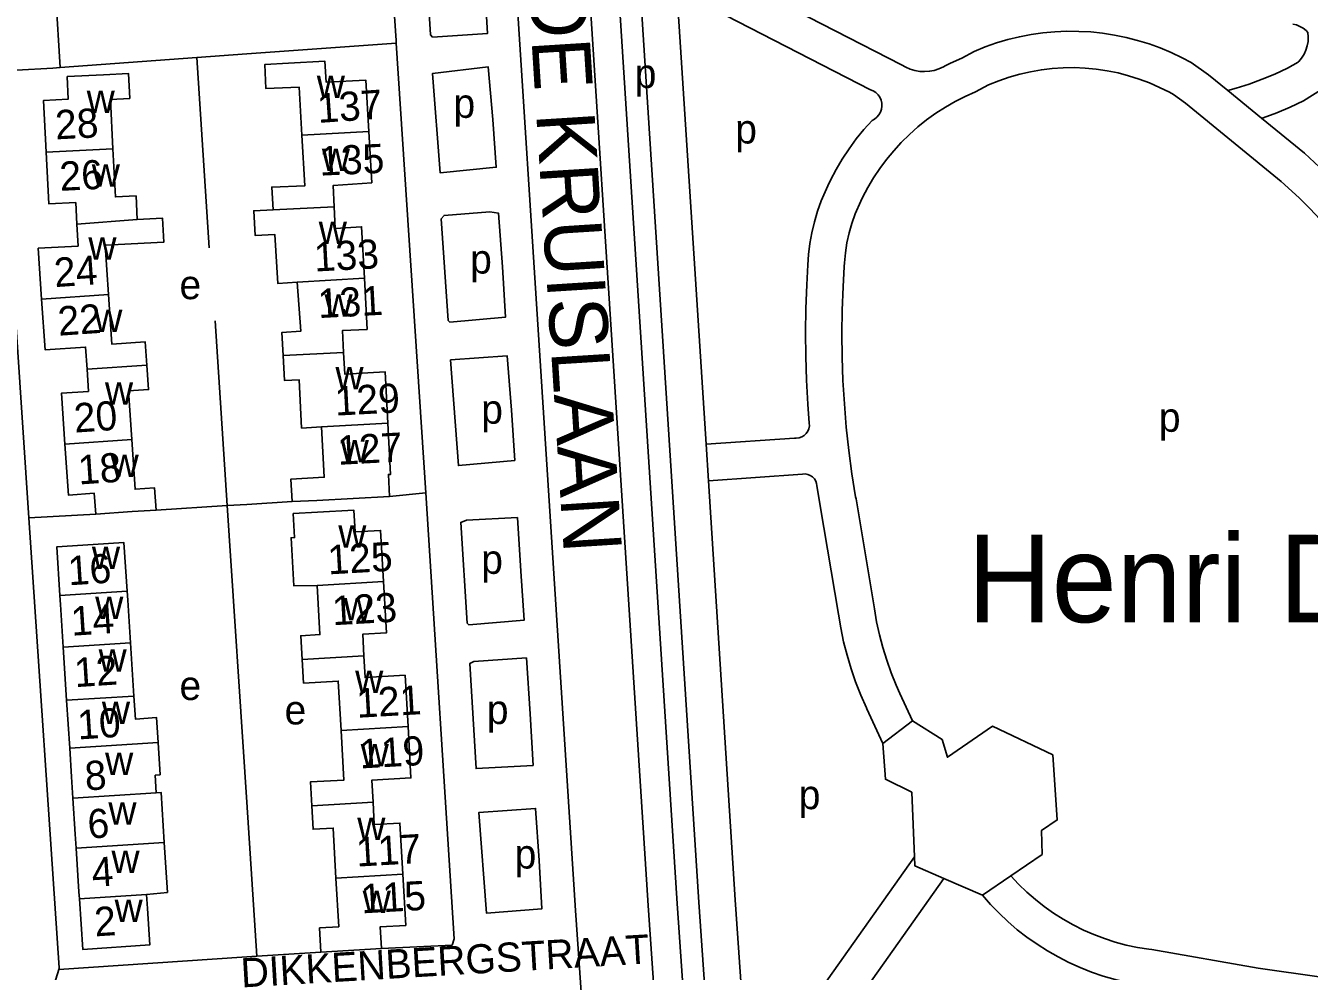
# Model space of a CAD drawing. Extents: x 159675 to 162108, y 386471 to 388472.
# Drawn here: x 160669.6 to 160845.9, y 388101.4 to 388231.2 of the extents above; entities that cross this region are included whole.
import ezdxf

# ---------------------------------------------------------------- set-up
doc = ezdxf.new("R2010")
doc.units = 0
for name, color, linetype in [('BLT_Basislijn', 7, 'Continuous'), ('BLT_Bebouwing', 7, 'Continuous'), ('BLT_Centroide', 7, 'Continuous'), ('BLT_Huisnummer', 7, 'Continuous'), ('BLT_Huisnummer_ tussenligend', 7, 'Continuous'), ('BLT_Onderverdeling_panden', 7, 'Continuous'), ('BLT_Sport_parknaam', 7, 'Continuous'), ('BLT_Straatnaam_hoofdweg', 7, 'Continuous'), ('BLT_Straatnaam_verkleind', 7, 'Continuous')]:
    doc.layers.add(name, color=color, linetype=linetype)

msp = doc.modelspace()

# ---------------------------------------------------------------- linework, layer by layer
at = {"layer": 'BLT_Basislijn'}
for p, q in [((160759.06, 388236.07), (160785.61, 388222.41)), ((160769.66, 388236.24), (160789.89, 388225.83)), ((160720.52, 388228.83), (160700, 388227.33)), ((160724.58, 388167.11), (160720.52, 388228.83)), ((160693.14, 388226.83), (160674.36, 388225.46)), ((160700, 388227.33), (160693.14, 388226.83)), ((160694.84, 388200.7), (160693.14, 388226.83)), ((160798.16, 388226.75), (160799.85, 388227.69)), ((160829.66, 388226.14), (160832.05, 388224.46)), ((160842.87, 388225.37), (160844.34, 388226.2)), ((160670.07, 388163.65), (160665.9, 388225.64)), ((160832.05, 388224.46), (160834.68, 388222.3)), ((160800.06, 388222.12), (160801.83, 388223.1)), ((160847.89, 388222.68), (160845.07, 388220.88)), ((160828.88, 388220.59), (160827.21, 388221.78)), ((160834.68, 388222.3), (160839.33, 388218.5)), ((160828.88, 388220.59), (160842.03, 388209.83)), ((160839.33, 388218.5), (160845.19, 388213.7)), ((160845.19, 388213.7), (160847.98, 388211.17)), ((160779.76, 388209.24), (160778.85, 388207.16)), ((160844.5, 388207.58), (160842.03, 388209.83)), ((160784.29, 388207.11), (160783.52, 388205.38)), ((160777.02, 388198.38), (160776.9, 388195.64)), ((160782.01, 388198.14), (160781.89, 388195.38)), ((160695.64, 388190.71), (160697.32, 388165.35)), ((160775.21, 388174.59), (160763.05, 388173.75)), ((160763.05, 388173.75), (160763.37, 388168.76)), ((160776.29, 388169.65), (160763.37, 388168.76)), ((160778.26, 388168.12), (160778.73, 388165.32)), ((160719.6, 388166.58), (160724.58, 388167.11)), ((160783.64, 388166.25), (160786.17, 388151.17)), ((160697.32, 388165.35), (160687.56, 388164.73)), ((160697.32, 388165.35), (160700, 388165.51)), ((160697.32, 388165.35), (160700, 388124.64)), ((160700, 388165.51), (160706.22, 388165.88)), ((160778.73, 388165.32), (160781.22, 388150.44)), ((160679.26, 388164.17), (160670.07, 388163.65)), ((160789.66, 388139.56), (160791.4, 388135.79)), ((160785.14, 388137.43), (160787.33, 388132.7)), ((160791.4, 388135.79), (160787.33, 388132.7)), ((160700, 388124.64), (160701.39, 388103.47)), ((160768.89, 388084.92), (160791.66, 388117.13)), ((160769.44, 388077.03), (160795.69, 388114.17)), ((160795.69, 388114.17), (160800.99, 388111.86)), ((160800.99, 388111.86), (160804.9, 388114.53)), ((160824.24, 388104.4), (160838.87, 388101.86)), ((160674.19, 388101.68), (160700, 388103.38)), ((160700, 388103.38), (160701.39, 388103.47)), ((160701.39, 388103.47), (160710.18, 388104.06)), ((160674.19, 388101.68), (160672.69, 388096.81)), ((160838.87, 388101.86), (160847.54, 388100.6))]:
    msp.add_line(p, q, dxfattribs=at)
for points in [[(160742.52, 388317.92), (160742.34, 388309.14), (160755.09, 388110.44), (160760.41, 388033.7)], [(160731.91, 388315.5), (160745.11, 388109.78), (160749.09, 388052.46)], [(160700, 388255.3), (160716.48, 388256.42), (160718.66, 388256.05), (160720.5, 388229.18), (160720.52, 388228.83)], [(160732.47, 388240.29), (160733.07, 388230.16), (160725.52, 388229.65), (160725.2, 388229.97), (160723.93, 388250.53), (160731.59, 388251.02)], [(160750.66, 388241.94), (160759.08, 388110.71), (160762.15, 388066.46)], [(160753.66, 388242.14), (160762.08, 388110.91), (160765.14, 388066.67), (160762.15, 388066.46)], [(160759.06, 388236.07), (160763.05, 388173.75)], [(160843.61, 388231.42), (160844.11, 388231.31), (160844.59, 388231.12), (160845.03, 388230.86), (160845.43, 388230.54), (160845.67, 388230.28)], [(160799.85, 388227.69), (160801.37, 388228.3), (160802.91, 388228.84), (160804.49, 388229.3), (160806.08, 388229.69), (160807.69, 388230), (160809.31, 388230.23), (160810.95, 388230.38), (160812.58, 388230.45), (160814.22, 388230.43), (160815.86, 388230.35), (160817.49, 388230.18), (160819.11, 388229.93), (160820.72, 388229.6), (160822.3, 388229.19), (160823.87, 388228.71), (160825.41, 388228.15), (160826.92, 388227.52), (160828.4, 388226.81), (160829.66, 388226.14)], [(160845.67, 388230.28), (160845.73, 388229.66), (160845.7, 388229.05), (160845.59, 388228.44), (160845.41, 388227.85), (160845.15, 388227.28), (160844.82, 388226.76), (160844.43, 388226.28), (160844.34, 388226.2)], [(160798.16, 388226.75), (160796.62, 388226.07), (160795.9, 388225.72)], [(160733.79, 388218.32), (160734.25, 388211.77), (160726.55, 388211.01), (160725.52, 388224.65), (160733.14, 388225.55), (160733.79, 388218.32)], [(160789.89, 388225.83), (160790.47, 388225.5), (160791.08, 388225.23), (160791.73, 388225.05), (160792.39, 388224.94), (160793.06, 388224.91), (160793.73, 388224.96), (160794.38, 388225.08), (160795.02, 388225.29), (160795.63, 388225.57), (160795.9, 388225.72)], [(160801.83, 388223.1), (160803.24, 388223.66), (160804.67, 388224.15), (160806.12, 388224.56), (160807.6, 388224.9), (160809.09, 388225.16), (160810.59, 388225.33), (160812.1, 388225.43), (160813.61, 388225.45), (160815.12, 388225.39), (160816.63, 388225.24), (160818.12, 388225.02), (160819.61, 388224.72), (160821.07, 388224.34), (160822.51, 388223.89), (160823.93, 388223.36), (160825.31, 388222.75), (160826.67, 388222.08), (160827.21, 388221.78)], [(160842.87, 388225.37), (160841.15, 388224.57), (160839.4, 388223.85), (160837.63, 388223.2), (160835.83, 388222.62), (160834.68, 388222.3)], [(160800.06, 388222.12), (160798.64, 388221.5), (160797.26, 388220.8), (160795.91, 388220.03), (160794.6, 388219.19), (160793.34, 388218.28), (160792.13, 388217.32), (160790.97, 388216.29), (160789.86, 388215.2), (160788.82, 388214.05), (160787.83, 388212.86), (160786.9, 388211.61), (160786.04, 388210.32), (160785.25, 388208.99), (160784.53, 388207.61), (160784.29, 388207.11)], [(160785.61, 388222.41), (160786, 388222.25), (160786.36, 388222.02), (160786.66, 388221.72), (160786.9, 388221.38), (160787.08, 388220.99), (160787.18, 388220.58), (160787.19, 388220.16), (160787.13, 388219.74), (160786.99, 388219.34), (160786.78, 388218.98), (160786.51, 388218.66), (160786.18, 388218.4), (160785.84, 388218.22)], [(160845.07, 388220.88), (160843.26, 388220.04), (160841.42, 388219.27), (160839.55, 388218.57), (160839.33, 388218.5)], [(160785.84, 388218.22), (160784.72, 388216.96), (160783.67, 388215.66), (160782.68, 388214.31), (160781.76, 388212.91), (160780.91, 388211.47), (160780.12, 388209.99), (160779.76, 388209.24)], [(160778.85, 388207.16), (160778.35, 388205.73), (160777.93, 388204.27), (160777.58, 388202.8), (160777.31, 388201.31), (160777.12, 388199.8), (160777.02, 388198.38)], [(160844.5, 388207.58), (160845.95, 388206.11), (160847.35, 388204.59), (160848.69, 388203.02), (160849.96, 388201.39), (160851.18, 388199.72), (160852.34, 388197.98)], [(160735.11, 388198.12), (160735.52, 388191.22), (160727.89, 388190.51), (160727.66, 388190.73), (160726.71, 388204.71), (160727.08, 388205.16), (160733.38, 388205.64), (160734.54, 388205.5), (160735.11, 388198.12)], [(160783.52, 388205.38), (160783.07, 388204.08), (160782.7, 388202.76), (160782.4, 388201.41), (160782.18, 388200.05), (160782.05, 388198.68), (160782.01, 388198.14)], [(160776.9, 388195.64), (160776.77, 388192.37), (160776.71, 388189.09), (160776.74, 388185.82), (160776.84, 388182.54), (160777.03, 388179.27), (160777.23, 388176.66)], [(160781.89, 388195.38), (160781.76, 388192.17), (160781.71, 388188.95), (160781.74, 388185.73), (160781.85, 388182.52), (160782.04, 388179.31), (160782.31, 388176.1), (160782.65, 388172.91), (160783.08, 388169.72), (160783.59, 388166.54), (160783.64, 388166.25)], [(160736.33, 388178.44), (160736.8, 388171.54), (160729.05, 388170.82), (160727.98, 388185.33), (160735.74, 388185.91), (160736.33, 388178.44)], [(160777.23, 388176.66), (160777.24, 388176.27), (160777.17, 388175.89), (160777.02, 388175.54), (160776.8, 388175.22), (160776.52, 388174.96), (160776.19, 388174.76), (160775.83, 388174.63), (160775.44, 388174.58), (160775.21, 388174.59)], [(160776.29, 388169.65), (160776.66, 388169.68), (160777.02, 388169.62), (160777.36, 388169.49), (160777.67, 388169.28), (160777.92, 388169.02), (160778.11, 388168.7), (160778.23, 388168.36), (160778.26, 388168.12)], [(160763.37, 388168.76), (160767.07, 388111.24), (160768.89, 388084.92)], [(160724.58, 388167.11), (160728.45, 388105.85), (160728.18, 388105.01), (160718.48, 388104.53)], [(160670.07, 388163.65), (160674.26, 388101.91), (160674.19, 388101.68)], [(160737.63, 388156.36), (160738.07, 388149.61), (160730.5, 388148.98), (160730.26, 388149.18), (160729.38, 388163.04), (160730.18, 388163.33), (160737.15, 388163.69), (160737.63, 388156.36)], [(160781.22, 388150.44), (160781.54, 388148.55), (160781.94, 388146.66), (160782.41, 388144.8), (160782.96, 388142.95), (160783.59, 388141.13), (160784.29, 388139.34), (160785.07, 388137.58), (160785.14, 388137.43)], [(160786.17, 388151.17), (160786.47, 388149.37), (160786.85, 388147.6), (160787.31, 388145.84), (160787.85, 388144.1), (160788.46, 388142.39), (160789.15, 388140.7), (160789.66, 388139.56)], [(160738.92, 388136.77), (160739.31, 388129.67), (160731.48, 388129.24), (160730.64, 388143.67), (160731.18, 388143.96), (160738.39, 388144.44), (160738.92, 388136.77)], [(160804.9, 388114.53), (160809.2, 388117.47), (160809.11, 388120.76), (160811.27, 388122.19), (160810.64, 388131.12), (160802.37, 388135.07), (160796.18, 388130.79), (160795.46, 388133.23), (160791.4, 388135.79)], [(160787.33, 388132.7), (160787.68, 388127.78), (160791.3, 388126), (160791.66, 388117.13)], [(160740.14, 388116.64), (160739.65, 388123.78), (160731.88, 388123.23), (160732.92, 388109.39), (160740.51, 388110), (160740.14, 388116.64)], [(160791.66, 388117.13), (160791.71, 388115.91), (160795.69, 388114.17)], [(160804.9, 388114.53), (160805.96, 388113.38), (160807.09, 388112.29), (160808.27, 388111.26), (160809.49, 388110.29), (160810.77, 388109.39), (160812.09, 388108.55), (160813.45, 388107.78), (160814.85, 388107.08), (160816.29, 388106.45), (160817.75, 388105.9), (160819.24, 388105.42), (160820.75, 388105.02), (160822.28, 388104.7), (160823.83, 388104.45), (160824.24, 388104.4)], [(160800.99, 388111.86), (160802.11, 388110.59), (160803.28, 388109.38), (160804.5, 388108.23), (160805.78, 388107.13), (160807.11, 388106.1), (160808.49, 388105.13), (160809.92, 388104.22), (160811.38, 388103.39), (160812.88, 388102.62), (160814.42, 388101.93), (160815.98, 388101.31), (160817.58, 388100.77), (160819.2, 388100.3), (160820.84, 388099.91), (160822.49, 388099.6), (160823.65, 388099.43)]]:
    msp.add_lwpolyline(points, dxfattribs=at)
at = {"layer": 'BLT_Bebouwing'}
for p, q in [((160673.64, 388237.98), (160674.36, 388225.46)), ((160674.43, 388151.78), (160674.35, 388153)), ((160683.57, 388153.59), (160683.65, 388152.38)), ((160684.02, 388146.49), (160683.65, 388152.38)), ((160674.8, 388145.9), (160674.43, 388151.78)), ((160675.27, 388138.61), (160674.8, 388145.9)), ((160684.49, 388139.2), (160684.02, 388146.49)), ((160675.69, 388132.05), (160675.27, 388138.61)), ((160688.12, 388128.36), (160687.83, 388132.83)), ((160675.95, 388128.11), (160675.69, 388132.05)), ((160676.13, 388125.19), (160675.95, 388128.11)), ((160676.45, 388120.22), (160676.13, 388125.19)), ((160676.57, 388118.32), (160676.45, 388120.22)), ((160689.11, 388112.23), (160688.67, 388119.1)), ((160676.96, 388112.33), (160676.57, 388118.32)), ((160677.02, 388111.37), (160676.96, 388112.33)), ((160689.11, 388112.23), (160686.24, 388111.96)), ((160718.48, 388104.53), (160710.18, 388104.06))]:
    msp.add_line(p, q, dxfattribs=at)
for points in [[(160707.58, 388216.17), (160707.19, 388222.79), (160702.63, 388222.57), (160702.46, 388225.87), (160705.74, 388226.05), (160710.73, 388226.33), (160710.89, 388223.46), (160716.35, 388223.73), (160716.75, 388216.69)], [(160668.39, 388225.12), (160673.38, 388225.4), (160674.36, 388225.46)], [(160672.46, 388213.86), (160672.11, 388220.96), (160675.5, 388221.13), (160675.35, 388224.22), (160680.34, 388224.47), (160683.76, 388224.65), (160683.93, 388221.23), (160681.29, 388221.1), (160681.63, 388214.32)], [(160703.62, 388205.94), (160703.43, 388209.05), (160707.99, 388209.24), (160707.58, 388216.17)], [(160712.01, 388206.33), (160711.88, 388209.29), (160717.16, 388209.65), (160716.75, 388216.69)], [(160676.68, 388203.95), (160676.53, 388206.94), (160672.82, 388206.76), (160672.46, 388213.86)], [(160684.97, 388204.61), (160684.81, 388207.85), (160681.97, 388207.71), (160681.63, 388214.32)], [(160706.92, 388196.03), (160704.25, 388195.84), (160703.85, 388202.55), (160701.13, 388202.42), (160700.95, 388205.82), (160703.62, 388205.94)], [(160716.14, 388196.57), (160715.77, 388203.61), (160712.15, 388203.36), (160712.01, 388206.33)], [(160671.83, 388193.69), (160671.36, 388200.66), (160676.83, 388200.97), (160676.68, 388203.95)], [(160681.03, 388194.32), (160680.57, 388201.08), (160688.6, 388201.49), (160688.43, 388204.78), (160684.97, 388204.61)], [(160704.99, 388185.94), (160704.82, 388189.12), (160707.42, 388189.26), (160706.92, 388196.03)], [(160713.28, 388186.37), (160713.13, 388189.35), (160716.51, 388189.53), (160716.14, 388196.57)], [(160686.29, 388184.61), (160686.07, 388187.8), (160681.49, 388187.49), (160681.03, 388194.32)], [(160678.07, 388184.05), (160677.86, 388187.1), (160672.31, 388186.72), (160671.83, 388193.69)], [(160710.28, 388176.13), (160707.53, 388175.98), (160707.18, 388182.61), (160705.17, 388182.51), (160704.99, 388185.94)], [(160719.37, 388176.66), (160719, 388183.69), (160713.44, 388183.4), (160713.28, 388186.37)], [(160675.03, 388173.78), (160674.56, 388180.76), (160678.27, 388181.01), (160678.07, 388184.05)], [(160684.21, 388174.4), (160683.76, 388181.07), (160686.52, 388181.26), (160686.29, 388184.61)], [(160719.6, 388166.58), (160719.44, 388169.61), (160719.74, 388169.63), (160719.37, 388176.66)], [(160706.22, 388165.88), (160706.06, 388168.98), (160710.64, 388169.22), (160710.28, 388176.13)], [(160679.26, 388164.17), (160679.06, 388167.03), (160675.51, 388166.79), (160675.03, 388173.78)], [(160687.56, 388164.73), (160687.35, 388167.77), (160684.67, 388167.59), (160684.21, 388174.4)], [(160719.6, 388166.58), (160709.61, 388166.06), (160706.22, 388165.88)], [(160687.56, 388164.73), (160684.25, 388164.51), (160679.26, 388164.17)], [(160718.76, 388154.9), (160718.36, 388161.94), (160714.88, 388161.74), (160714.71, 388164.71), (160709.72, 388164.43), (160706.37, 388164.24), (160706.56, 388160.95), (160706.08, 388160.93), (160706.45, 388154.33), (160709.67, 388154.39)], [(160674.35, 388153), (160673.92, 388159.67), (160678.91, 388159.99), (160683.14, 388160.27), (160683.57, 388153.59)], [(160709.67, 388154.39), (160710.05, 388147.63), (160707.42, 388147.48), (160707.61, 388144.23)], [(160718.76, 388154.9), (160719.16, 388147.86), (160715.92, 388147.67), (160716.09, 388144.71)], [(160707.61, 388144.23), (160707.79, 388140.97), (160712.56, 388141.24), (160712.94, 388134.48)], [(160716.09, 388144.71), (160716.25, 388141.74), (160721.74, 388142.05), (160722.14, 388135)], [(160687.83, 388132.83), (160687.61, 388136.23), (160684.7, 388136.04), (160684.49, 388139.2)], [(160712.94, 388134.48), (160713.33, 388127.66), (160708.74, 388127.4), (160708.93, 388124.13)], [(160722.14, 388135), (160722.54, 388127.95), (160717.16, 388127.64), (160717.33, 388124.61)], [(160687.58, 388125.92), (160687.43, 388128.32), (160688.12, 388128.36)], [(160688.67, 388119.1), (160688.23, 388125.97), (160687.58, 388125.92)], [(160708.93, 388124.13), (160709.11, 388120.91), (160711.86, 388121.07), (160712.24, 388114.22)], [(160717.33, 388124.61), (160717.5, 388121.57), (160721.03, 388121.77), (160721.43, 388114.74)], [(160710.18, 388104.06), (160709.99, 388107.37), (160712.62, 388107.52), (160712.24, 388114.22)], [(160721.43, 388114.74), (160721.83, 388107.71), (160718.31, 388107.51), (160718.48, 388104.53)], [(160686.24, 388111.96), (160686.37, 388110.02), (160686.69, 388105.03), (160677.47, 388104.43), (160677.02, 388111.37)]]:
    msp.add_lwpolyline(points, dxfattribs=at)
at = {"layer": 'BLT_Onderverdeling_panden'}
for p, q in [((160716.75, 388216.69), (160707.58, 388216.17)), ((160672.46, 388213.86), (160681.63, 388214.32)), ((160712.01, 388206.33), (160703.62, 388205.94)), ((160676.68, 388203.95), (160684.97, 388204.61)), ((160716.14, 388196.57), (160706.92, 388196.03)), ((160671.83, 388193.69), (160681.03, 388194.32)), ((160713.28, 388186.37), (160704.99, 388185.94)), ((160678.07, 388184.05), (160686.29, 388184.61)), ((160719.37, 388176.66), (160710.28, 388176.13)), ((160675.03, 388173.78), (160684.21, 388174.4)), ((160718.76, 388154.9), (160709.67, 388154.39)), ((160683.57, 388153.59), (160674.35, 388153)), ((160684.02, 388146.49), (160674.8, 388145.9)), ((160716.09, 388144.71), (160707.61, 388144.23)), ((160684.49, 388139.2), (160675.27, 388138.61)), ((160722.14, 388135), (160712.94, 388134.48)), ((160687.83, 388132.83), (160675.69, 388132.05)), ((160687.58, 388125.92), (160676.13, 388125.19)), ((160717.33, 388124.61), (160708.93, 388124.13)), ((160688.67, 388119.1), (160676.57, 388118.32)), ((160721.43, 388114.74), (160712.24, 388114.22)), ((160686.24, 388111.96), (160677.02, 388111.37))]:
    msp.add_line(p, q, dxfattribs=at)

# ---------------------------------------------------------------- texts
at = {"layer": 'BLT_Centroide'}
for s, p in [('w', (160709.61, 388221.28)), ('p', (160753.26, 388222.66)), ('w', (160678.02, 388219.23)), ('p', (160728.38, 388218.56)), ('p', (160767.06, 388215.04)), ('w', (160710.3, 388211.28)), ('w', (160678.72, 388209.12)), ('w', (160709.88, 388201.23)), ('w', (160678.25, 388199.08)), ('p', (160730.67, 388197.19)), ('e', (160690.76, 388193.67)), ('w', (160710.67, 388191.27)), ('w', (160679.06, 388189.16)), ('w', (160712.17, 388181.3)), ('w', (160680.53, 388179.19)), ('p', (160732.19, 388176.58)), ('p', (160825.22, 388175.47)), ('w', (160712.89, 388171.27)), ('w', (160681.3, 388169.25)), ('w', (160712.56, 388159.58)), ('w', (160678.74, 388156.62)), ('p', (160732.19, 388155.97)), ('w', (160679.19, 388149.75)), ('w', (160713.28, 388149.58)), ('w', (160679.65, 388142.56)), ('e', (160690.76, 388138.65)), ('w', (160714.88, 388139.61)), ('w', (160680.11, 388135.34)), ('e', (160705.19, 388135.3)), ('p', (160732.96, 388135.36)), ('w', (160715.64, 388129.56)), ('w', (160680.55, 388128.34)), ('p', (160775.78, 388123.67)), ('w', (160681, 388121.53)), ('w', (160715.17, 388119.42)), ('p', (160736.77, 388115.52)), ('w', (160681.42, 388114.91)), ('w', (160715.91, 388109.41)), ('w', (160681.85, 388108.19))]:
    msp.add_text(s, height=4, dxfattribs=at).set_placement(p)
at = {"layer": 'BLT_Huisnummer'}
for s, rotation, p in [('137', 3.889, (160709.81, 388217.86)), ('28', 2.8901, (160673.78, 388215.6)), ('131', 3.0015, (160709.86, 388191.07)), ('22', 3.8891, (160674.18, 388188.65)), ('127', 3.0151, (160712.54, 388170.93)), ('18', 3.8872, (160676.96, 388168.23)), ('16', 3.678, (160675.56, 388154.39)), ('123', 3.2374, (160711.81, 388148.91)), ('10', 3.6718, (160676.86, 388133.23)), ('119', 3.2353, (160715.56, 388129.25)), ('6', 3.6726, (160678.26, 388119.62)), ('115', 3.2391, (160715.78, 388109.36)), ('2', 3.6734, (160679.19, 388106.2))]:
    msp.add_text(s, height=4, rotation=rotation, dxfattribs=at).set_placement(p)
at = {"layer": 'BLT_Huisnummer_ tussenligend'}
for s, rotation, p in [('135', 2.6212, (160710.04, 388210.62)), ('26', 2.8903, (160674.39, 388208.53)), ('133', 3.0167, (160709.32, 388197.46)), ('24', 3.8947, (160673.67, 388195.32)), ('129', 3.0098, (160712.19, 388177.68)), ('20', 3.8891, (160676.4, 388175.35)), ('125', 3.2374, (160711.2, 388155.89)), ('14', 3.673, (160675.97, 388147.47)), ('12', 3.6734, (160676.43, 388140.41)), ('121', 3.2375, (160715.16, 388136.21)), ('8', 3.6784, (160677.88, 388126.23)), ('117', 3.2399, (160715.12, 388115.78)), ('4', 3.673, (160678.82, 388113))]:
    msp.add_text(s, height=4, rotation=rotation, dxfattribs=at).set_placement(p)
at = {"layer": 'BLT_Sport_parknaam'}
msp.add_text('Henri Dunant Park', height=12, dxfattribs=at).set_placement((160798.92, 388149.33))
at = {"layer": 'BLT_Straatnaam_hoofdweg'}
msp.add_text('RODE KRUISLAAN', height=8, rotation=273.6049, dxfattribs=at).set_placement((160737.6, 388252.99))
at = {"layer": 'BLT_Straatnaam_verkleind'}
msp.add_text('DIKKENBERGSTRAAT', height=4, rotation=3.3851, dxfattribs=at).set_placement((160699.29, 388099.19))

doc.saveas('drawing.dxf')
